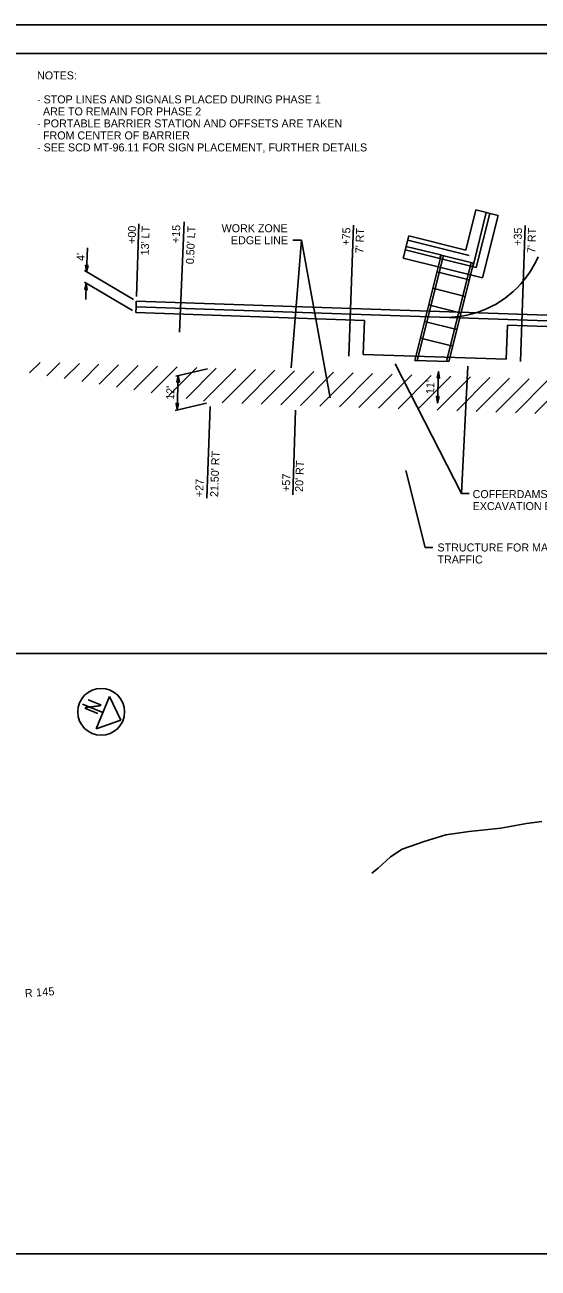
# Model space of a CAD drawing. Extents: x 0 to 685, y -440 to 971.
# Drawn here: x 234 to 413.5, y 5 to 440 of the extents above; entities that cross this region are included whole.
import ezdxf

# ---------------------------------------------------------------- set-up
doc = ezdxf.new("R2010")
doc.units = 0
for name, color, linetype in [('_CIVIL_CONSTRUCTION', 7, 'Continuous'), ('GE_P_Alignment', 7, 'Continuous'), ('GE_P_Alignment_100_Cardinal_Points', 7, 'Continuous'), ('GE_P_Alignment_100_Curve_Data', 7, 'Continuous'), ('GE_P_Alignment_100_Distances', 7, 'Continuous'), ('GE_P_Alignment_100_Stations', 7, 'Continuous'), ('PF_P_Grade_Line', 7, 'Continuous'), ('PF_X_Ground_Line', 7, 'Continuous'), ('PV_P_EOP', 7, 'Continuous'), ('TX_P_20', 7, 'Continuous')]:
    doc.layers.add(name, color=color, linetype=linetype)

msp = doc.modelspace()

# ---------------------------------------------------------------- linework, layer by layer
at = {"layer": '_CIVIL_CONSTRUCTION'}
msp.add_lwpolyline([(0, 0), (680, 0), (680, 440), (0, 440)], close=True, dxfattribs=at)
at = {"layer": 'GE_P_Alignment'}
msp.add_lwpolyline([(30, 430), (670, 430), (670, 10), (30, 10)], close=True, dxfattribs=at)
at = {"layer": 'GE_P_Alignment_100_Cardinal_Points'}
for p, q in [((30, 220), (640, 220)), ((263.61, 205.06), (258.94, 193.68)), ((267.59, 196.78), (263.61, 205.06)), ((261.27, 199.37), (254.12, 202.31)), ((258.94, 193.68), (267.59, 196.78))]:
    msp.add_line(p, q, dxfattribs=at)
msp.add_circle((260.67, 199.62), 8.2, dxfattribs=at)
at = {"layer": 'GE_P_Alignment_100_Curve_Data'}
for p, q in [((273.02, 344.92), (273.89, 370.38)), ((288.09, 332.48), (289.76, 371.13)), ((348.91, 369.9), (347.35, 324.12)), ((408.95, 369.8), (407.32, 322.19)), ((255.59, 353.61), (255.87, 362.04)), ((327.12, 319.98), (330.73, 364.7)), ((330.73, 364.7), (327.75, 364.7)), ((340.83, 309.5), (330.73, 364.7)), ((272.02, 343.89), (254.83, 354.06)), ((271.59, 340.07), (254.9, 349.93)), ((255.26, 343.93), (255.45, 349.61)), ((297.88, 319.62), (286.84, 317.09)), ((363.55, 321.43), (386.75, 276)), ((378.31, 307.72), (378.69, 318.71)), ((388.9, 320.59), (386.75, 276)), ((287.66, 317.28), (287.25, 305.28)), ((297.47, 307.63), (286.6, 305.13)), ((298.75, 306.42), (297.66, 274.38)), ((328.69, 305.17), (327.68, 275.58)), ((367.29, 284.09), (374.04, 257.15)), ((386.75, 276), (389.44, 276)), ((386.75, 276), (389.44, 276)), ((374.04, 257.15), (376.73, 257.15))]:
    msp.add_line(p, q, dxfattribs=at)
for points in [[(30, 10), (30, 430), (640, 430), (640, 10)], [(256.12, 355.85), (255.59, 353.61), (255.21, 355.88)], [(254.92, 347.37), (255.45, 349.61), (255.83, 347.34)], [(378.16, 316.47), (378.69, 318.71), (379.07, 316.44)], [(287.13, 315.03), (287.66, 317.28), (288.04, 315)], [(378.85, 309.96), (378.31, 307.72), (377.94, 309.99)], [(287.78, 307.52), (287.25, 305.28), (286.87, 307.56)]]:
    msp.add_lwpolyline(points, close=True, dxfattribs=at)
at = {"layer": 'GE_P_Alignment_100_Distances'}
for p, q in [((272.9, 341.34), (272.83, 339.34)), ((352.78, 336.61), (272.83, 339.34)), ((463.68, 334.82), (272.9, 341.34)), ((352.78, 336.61), (352.37, 324.67)), ((402.75, 334.9), (402.35, 323.05)), ((463.61, 332.82), (402.75, 334.9)), ((352.37, 324.67), (402.35, 323.05))]:
    msp.add_line(p, q, dxfattribs=at)
for start, end in [(287.5066, 336.7948), (268.0436, 287.5066)]:
    msp.add_arc((381.35, 372.65), 35, start, end, dxfattribs=at)
at = {"layer": 'GE_P_Alignment_100_Stations'}
for p, q in [((391.74, 375.25), (388.24, 361.18)), ((395.38, 374.34), (390.98, 356.63)), ((391.74, 375.25), (399.51, 373.32)), ((396.59, 374.04), (391.89, 355.12)), ((399.51, 373.32), (394.08, 351.48)), ((368.27, 366.14), (366.34, 358.38)), ((388.24, 361.18), (368.27, 366.14)), ((379.19, 358.27), (367.06, 361.29)), ((379.49, 359.49), (367.36, 362.5)), ((389.34, 359.36), (367.91, 364.68)), ((394.08, 351.48), (366.34, 358.38)), ((379.58, 359.47), (370.41, 322.59)), ((380.38, 359.26), (371.26, 322.56)), ((379.49, 359.49), (379.19, 358.27)), ((379.19, 358.27), (391.89, 355.12)), ((379.58, 359.47), (379.49, 359.49)), ((379.58, 359.47), (390.9, 356.65)), ((390.09, 356.85), (381.48, 322.23)), ((378.13, 353.64), (389.45, 350.83)), ((390.9, 356.65), (382.34, 322.2)), ((390.98, 356.63), (390.68, 355.42)), ((390.98, 356.63), (390.9, 356.65)), ((376.68, 347.82), (388, 345.01)), ((375.23, 342), (386.56, 339.18)), ((373.79, 336.17), (385.11, 333.36)), ((372.34, 330.35), (383.66, 327.54)), ((370.41, 322.59), (382.34, 322.2))]:
    msp.add_line(p, q, dxfattribs=at)
at = {"layer": 'PF_P_Grade_Line'}
msp.add_circle((260.67, 199.62), 8.2, dxfattribs=at)
at = {"layer": 'PF_X_Ground_Line'}
for p, q in [((239.35, 321.92), (235.62, 318.2)), ((246.22, 321.72), (241.71, 317.21)), ((253.07, 321.5), (247.79, 316.22)), ((259.91, 321.27), (253.87, 315.23)), ((266.75, 321.04), (259.96, 314.25)), ((273.58, 320.8), (266.04, 313.26)), ((280.42, 320.57), (272.12, 312.27)), ((287.26, 320.34), (278.2, 311.28)), ((294.1, 320.1), (284.29, 310.29)), ((300.93, 319.87), (290.37, 309.3)), ((307.77, 319.64), (296.45, 308.32)), ((314.61, 319.4), (303, 307.79)), ((321.45, 319.17), (309.84, 307.56)), ((328.28, 318.93), (316.67, 307.32)), ((335.12, 318.7), (323.51, 307.09)), ((341.96, 318.47), (330.35, 306.86)), ((348.8, 318.23), (337.19, 306.62)), ((355.63, 318), (344.02, 306.39)), ((362.47, 317.77), (350.86, 306.16)), ((369.31, 317.53), (357.7, 305.92)), ((376.15, 317.3), (364.54, 305.69)), ((382.98, 317.07), (371.37, 305.46)), ((389.82, 316.83), (378.21, 305.22)), ((396.66, 316.6), (385.05, 304.99)), ((403.5, 316.37), (391.89, 304.76)), ((410.33, 316.13), (398.72, 304.52)), ((417.17, 315.9), (405.56, 304.29)), ((424.01, 315.67), (412.4, 304.05))]:
    msp.add_line(p, q, dxfattribs=at)
msp.add_lwpolyline([(271.01, 312.01), (271.01, 312.01)], close=True, dxfattribs=at)
at = {"layer": 'PV_P_EOP'}
msp.add_lwpolyline([(355.3, 143.14), (357.52, 144.9), (361.88, 148.95), (365.98, 151.54), (373.7, 154.25), (381.22, 156.57), (389.42, 157.82), (400.45, 158.96), (409.5, 160.53), (414.83, 161.23)], dxfattribs=at)
at = {"layer": 'TX_P_20'}
for q in [(272.9, 341.34), (463.75, 336.82)]:
    msp.add_line((272.96, 343.34), q, dxfattribs=at)

# ---------------------------------------------------------------- texts
at = {"layer": 'GE_P_Alignment_100_Cardinal_Points'}
msp.add_text('N', height=5, rotation=247.6505, dxfattribs=at).set_placement((256.43, 204.64))
at = {"layer": 'GE_P_Alignment_100_Curve_Data'}
for s, p in [('NOTES:', (238.25, 420.92)), ('- STOP LINES AND SIGNALS PLACED DURING PHASE 1', (238.25, 412.52)), ('  ARE TO REMAIN FOR PHASE 2', (238.25, 408.32)), ('- PORTABLE BARRIER STATION AND OFFSETS ARE TAKEN', (238.25, 404.12)), ('  FROM CENTER OF BARRIER', (238.25, 399.92)), ('- SEE SCD MT-96.11 FOR SIGN PLACEMENT, FURTHER DETAILS', (238.25, 395.72)), ('WORK ZONE', (302.81, 367.44)), ('EDGE LINE', (306.07, 363.24)), ('STRUCTURE FOR MAINTAINING', (378.32, 255.75)), ('TRAFFIC', (378.32, 251.55))]:
    msp.add_text(s, height=2.8, dxfattribs=at).set_placement(p)
for s, rotation, p in [('+15', 87.5249, (288.13, 363.6)), ('+00', 88.0436, (272.72, 363.33)), ("13' LT", 88.0436, (277.3, 359.31)), ("0.50' LT", 87.5249, (293.11, 356.22)), ('+75', 88.0436, (347.67, 362.7)), ("7' RT", 88.0436, (352.36, 360.02)), ('+35', 88.0436, (407.68, 362.65)), ("7' RT", 88.0436, (412.49, 360.1)), ("4'", 88.0951, (254.88, 357.34)), ("12'", 88.0436, (286.17, 308.76)), ("11'", 88.0436, (377.11, 310.77)), ("21.50' RT", 88.0436, (301.58, 274.74)), ("20' RT", 88.0436, (331.26, 276.56)), ('+57', 88.0436, (326.68, 276.56)), ('+27', 88.0436, (296.33, 274.74)), ('R', 4.1927, (234.1, 99.77)), ('1', 4.1927, (238, 100.05)), ('4', 4.1927, (240.17, 100.21)), ('5', 4.1927, (242.33, 100.37))]:
    msp.add_text(s, height=2.8, rotation=rotation, dxfattribs=at).set_placement(p)
at = {"layer": 'PF_X_Ground_Line'}
for s, p in [('COFFERDAMS AND', (390.61, 274.42)), ('EXCAVATION BRACING', (390.61, 270.22))]:
    msp.add_text(s, height=2.8, dxfattribs=at).set_placement(p)

doc.saveas('drawing.dxf')
